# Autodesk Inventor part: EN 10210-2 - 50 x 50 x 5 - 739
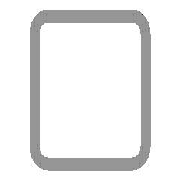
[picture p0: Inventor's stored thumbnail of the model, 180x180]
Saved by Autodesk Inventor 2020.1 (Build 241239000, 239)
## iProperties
Created: 2019-01
Part Number: EN 10210-2 - 50 x 50 x 5 - 739
Material: Stahl, weich
Description: Rohrleitung
Document SubType Name: Modeling
Standard: DIN
Designer: lutzd
Standard Revision: 2006-07
Standards Organization: DIN
Language: de-DE
Size Designation: 50 x 50 x 5
Categories: <MemberInstance><Categories><Category DisplayName="Profile" InternalName="089c4875-fa83-4c05-b084-43b9cc11f5ed" Mnemonic="GRDR"><CategoryParameter DisplayName="
Stock Number: 50 x 50 x 5
Mass: 5036.06 g
Surface Area: 2517.71 cm^2
Volume: 641.536 cm^3
Density: 7.85 g/cm^3
Appearance: Semi-Polished(8)
_CCFamilyMember: 16
_CCFamilyDisplayName: DIN EN 10210-2 (USAS B17.1 quadratisch) - Rohrleitung — In Klammern angegebene Größen wurden aufgehoben
_FrameMemberDoc: Frame Member File
_Version: 15.0.0
_GetPNFromCC: 1
IsCustomPart: 1
G_L: 739,000 mm
G_W: 50,000 mm
G_H: 50,000 mm
DocNumber: ADSK-014332
Folder: .
Dimensions: 50x50x739 mm
Mass: 5,036 kg
Title: Profil-Bauteil
Author: lutzd
Revision Number: -
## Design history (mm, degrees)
node "Startebene"
node "Endebene"
sketch "Skizze"
  geometry: L1 (-25, -17.5)-(-25, 17.5); L2 (-17.5, 25)-(17.5, 25); L3 (25, 17.5)-(25, -17.5); L4 (17.5, -25)-(-17.5, -25); L5 (-15, 20)-(15, 20); L6 (20, 15)-(20, -15); L7 (15, -20)-(-15, -20); L8 (-20, -15)-(-20, 15); L9 (0, 37.175)-(0, -37.175) reference; L10 (-37.175, 0)-(37.175, 0) reference; A1 r 7.5 centre (-17.5, -17.5) between (-25, -17.5) and (-17.5, -25); A2 r 7.5 centre (-17.5, 17.5) between (-17.5, 25) and (-25, 17.5); A3 r 7.5 centre (17.5, 17.5) between (25, 17.5) and (17.5, 25); A4 r 7.5 centre (17.5, -17.5) between (17.5, -25) and (25, -17.5); A5 r 5 centre (-15, -15) between (-20, -15) and (-15, -20); A6 r 5 centre (-15, 15) between (-15, 20) and (-20, 15); A7 r 5 centre (15, 15) between (20, 15) and (15, 20); A8 r 5 centre (15, -15) between (15, -20) and (20, -15)
  constraints: 16 end point, 16 point on circle, 16 tangent, 8 centre point, 6 equal radius, 4 parallel, 2 perpendicular, 2 other
  dimensions: "d7" = 7.5 radius of A1 (= G_IR); "d10" = 50 distance between parallel lines of L2 L4 (= G_H); "d11" = 50 distance between parallel lines of L1 L3 (= G_W); "d12" = 5 distance between parallel lines of L3 L6 (= G_T); "d15" = 25 distance between parallel lines of L2 L10 (= 0.5 x d10); "d16" = 25 distance between parallel lines of L9 L3 (= 0.5 x d11); "d19" = 5 radius of A5 (= G_T); "d20" = 5 distance between parallel lines of L4 L7 (= G_T)
extrude "Körper" new body sketch "Skizze" stored distance "d3" = 739 (= G_L); taper "d4" = 0 deg
node "Driven Length"
  sketch "Sketch3"
    geometry: L1 (0, 0)-(10, 0) reference
    constraints: 2 end point, 1 horizontal
  workplane "Work Plane3"
  sketch "Sketch4"
    geometry: L1 (-2, 0)-(12, 0) reference; L2 (-2, 739)-(12, 739) reference
    dimensions: "d18" = 739 distance between parallel lines of L1 L2 (derived)
sketch "Skizze5"
  geometry: L1 (739, 0)-(739, -35) reference; L2 (739, -17.5)-(494.75, -17.5); 4 further points
  constraints: 4 end point, 2 point on line, 1 coincident, 1 horizontal, 1 midpoint, 1 vertical, 2 other
  dimensions: "d21" = 91.75 distance from line of L1 point (647.25, -17.5); "d22" = 152.5 distance of point (494.75, -17.5) point (647.25, -17.5); "d23" = 76.25 distance of point (494.75, -17.5) point (571, -17.5) (= 0.5 x d22)
hole "Bohrung1" sketch "Skizze5" at (647.25, -17.5), (571, -17.5), (494.75, -17.5) diameter "d24" = 12; stored, may be unused: countersink angle "d28" = 90 deg, drill point angle "d30" = 118 deg; dims "d25" = 20, "d26" = 4, "d27" = 2, "d29" = 8
sketch "Skizze6"
  geometry: L1 (35, 0)-(0, 0) reference; L2 (17.5, 0)-(17.5, 418.25); 2 further points
  constraints: 2 end point, 1 coincident, 1 point on line, 1 vertical
  dimensions: "d31" = 21.25 distance from line of L1 point (17.5, 21.25); "d32" = 397 distance of point (17.5, 418.25) point (17.5, 21.25)
hole "Bohrung2" sketch "Skizze6" at (17.5, 21.25), (17.5, 418.25) diameter "d33" = 6.647; stored, may be unused: countersink angle "d37" = 90 deg, drill point angle "d39" = 118 deg; dims "d34" = 16, "d35" = 4, "d36" = 2, "d38" = 22.2
body "Solid1"
other parameters: "G_W" = 50 [user parameter; used in 1 equation term], "G_H" = 50 [user parameter; used in 1 equation term], "G_T" = 5 [user parameter; used in 3 equation terms], "G_IR" = 7.5 [user parameter; used in 1 equation term], "G_L" = 739 (= d18) [user parameter; used in 1 equation term], "G_OFFSET_START" = 0 [user parameter; used in 1 equation term], "G_OFFSET_END" = 0 [user parameter; used in 1 equation term], "d13" = 0 (computed from G_OFFSET_START), "d14" = 739 (= G_OFFSET_END + B_L), "B_L" = 739 [user parameter; used in 1 equation term], "d17" = 90 deg
